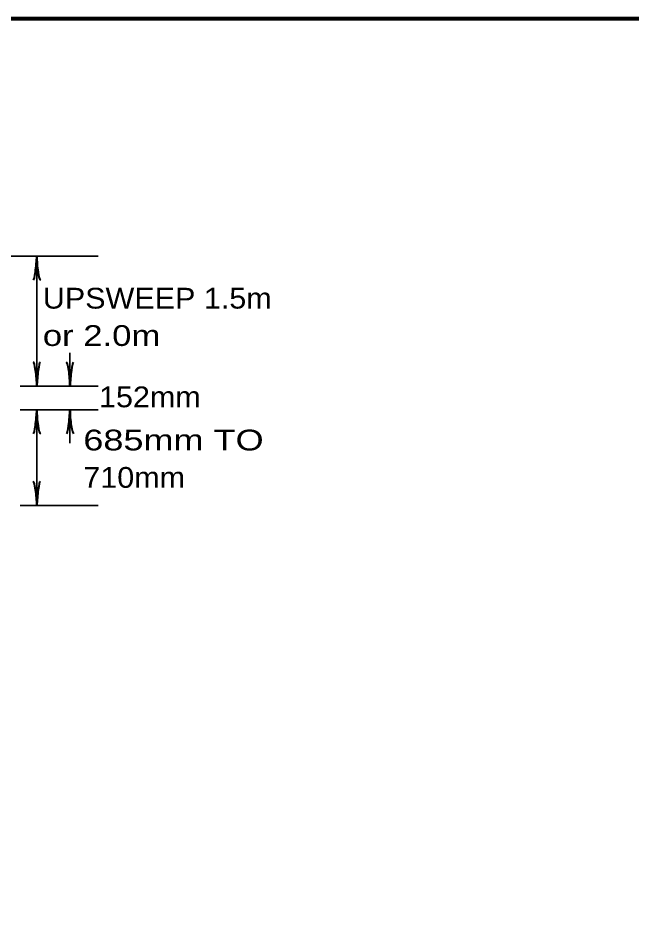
# Model space of a CAD drawing. Extents: x -32 to 824, y -12 to 532.
# Drawn here: x 168.1 to 256.9, y 394.1 to 525.2 of the extents above; entities that cross this region are included whole.
import ezdxf

# ---------------------------------------------------------------- set-up
doc = ezdxf.new("R2010")
doc.units = 0
doc.header["$LTSCALE"] = 1.2
doc.layers.add('1', color=7, linetype='Continuous', lineweight=13)

msp = doc.modelspace()

# ---------------------------------------------------------------- linework, layer by layer
at = {"layer": '1', "lineweight": 35}
for p, q in [((179.657, 490.821), (103.002, 490.821)), ((170.802, 472.071), (170.802, 490.821)), ((175.602, 472.071), (175.602, 476.871)), ((168.402, 472.071), (179.657, 472.071)), ((168.402, 468.621), (179.657, 468.621)), ((170.802, 454.821), (170.802, 468.621)), ((175.602, 463.821), (175.602, 468.621)), ((168.402, 454.821), (179.657, 454.821))]:
    msp.add_line(p, q, dxfattribs=at)
at = {"layer": '1', "lineweight": 158}
msp.add_lwpolyline([(817.469, 525.227), (25.769, 525.127), (25.869, -0.873)], dxfattribs=at)
at = {"layer": '1', "lineweight": 40}
for centre, major_axis, ratio, start_param, end_param in [((170.548, 489.476), (0.211, 2.108), 0.07063, 3.1407148, 5.41811), ((170.548, 489.476), (0.211, 2.108), 0.07063, 3.1407148, 5.41811), ((171.134, 489.511), (-0.187, 2.143), 0.122415, 0.8963533, 3.1415927), ((171.134, 489.511), (-0.187, 2.143), 0.122415, 0.8963533, 3.1415927), ((170.471, 473.38), (0.187, -2.143), 0.122415, 0.8963533, 3.1415927), ((170.471, 473.38), (0.187, -2.143), 0.122415, 0.8963533, 3.1415927), ((171.056, 473.415), (-0.211, -2.108), 0.07063, 3.1407148, 5.41811), ((171.056, 473.415), (-0.211, -2.108), 0.07063, 3.1407148, 5.41811), ((175.271, 473.38), (0.187, -2.143), 0.122415, 0.8963533, 3.1415927), ((175.271, 473.38), (0.187, -2.143), 0.122415, 0.8963533, 3.1415927), ((175.856, 473.415), (-0.211, -2.108), 0.07063, 3.1407148, 5.41811), ((175.856, 473.415), (-0.211, -2.108), 0.07063, 3.1407148, 5.41811), ((170.548, 467.276), (0.211, 2.108), 0.07063, 3.1407148, 5.41811), ((170.548, 467.276), (0.211, 2.108), 0.07063, 3.1407148, 5.41811), ((171.134, 467.311), (-0.187, 2.143), 0.122415, 0.8963533, 3.1415927), ((171.134, 467.311), (-0.187, 2.143), 0.122415, 0.8963533, 3.1415927), ((175.348, 467.276), (0.211, 2.108), 0.07063, 3.1407148, 5.41811), ((175.348, 467.276), (0.211, 2.108), 0.07063, 3.1407148, 5.41811), ((175.934, 467.311), (-0.187, 2.143), 0.122415, 0.8963533, 3.1415927), ((175.934, 467.311), (-0.187, 2.143), 0.122415, 0.8963533, 3.1415927), ((170.471, 456.13), (0.187, -2.143), 0.122415, 0.8963533, 3.1415927), ((170.471, 456.13), (0.187, -2.143), 0.122415, 0.8963533, 3.1415927), ((171.056, 456.165), (-0.211, -2.108), 0.07063, 3.1407148, 5.41811), ((171.056, 456.165), (-0.211, -2.108), 0.07063, 3.1407148, 5.41811)]:
    msp.add_ellipse(centre, major_axis=major_axis, ratio=ratio, start_param=start_param, end_param=end_param, dxfattribs=at)

# ---------------------------------------------------------------- texts
at = {"layer": '1'}
for s, width, p in [('UPSWEEP 1.5m', 1.1, (171.672, 483.259)), ('or 2.0m', 1.25, (171.672, 477.859)), ('152mm', 1.1, (179.8, 469.001)), ('685mm TO', 1.3, (177.531, 462.763)), ('710mm', 1.1, (177.531, 457.363))]:
    msp.add_text(s, height=3, dxfattribs=dict(at, width=width)).set_placement(p)

doc.saveas('drawing.dxf')
